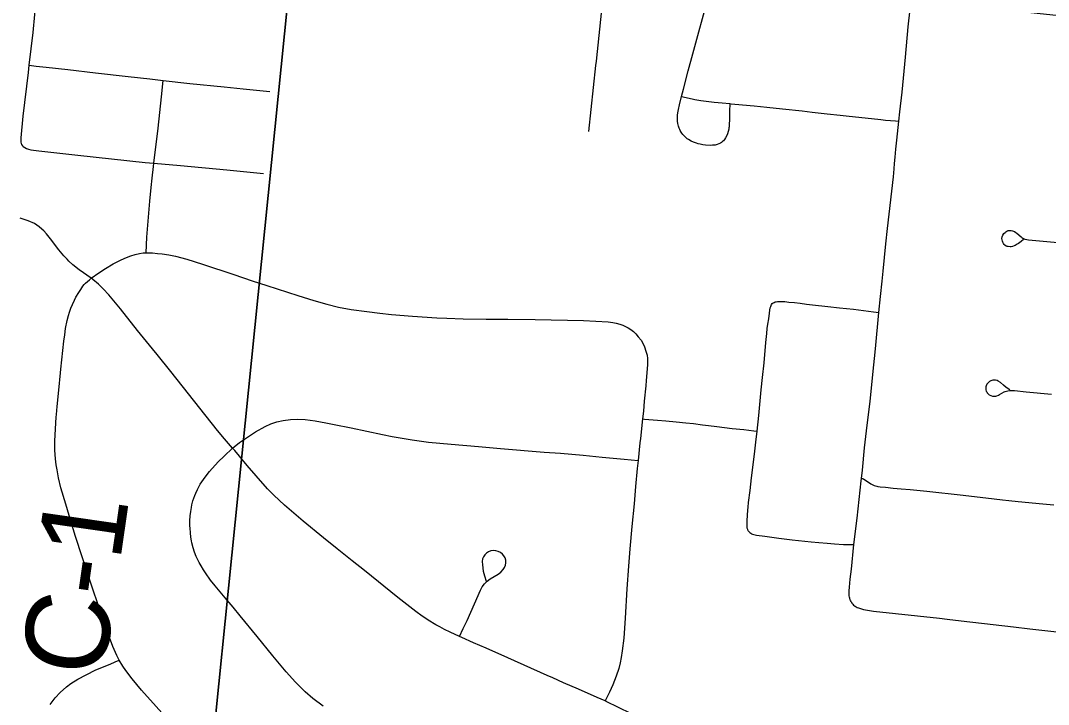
# Model space of a CAD drawing. Extents: x 0 to 34, y 0 to 22.
# Drawn here: x 24.732 to 25.43, y 15.225 to 15.69 of the extents above; entities that cross this region are included whole.
import ezdxf

# ---------------------------------------------------------------- set-up
doc = ezdxf.new("R2010")
doc.units = 0
for name, color, linetype in [('GM_X_City_Street', 7, 'Continuous'), ('GM_X_County_Road_Text', 7, 'Continuous'), ('GM_X_Section', 7, 'Continuous'), ('GM_X_Township_Road', 7, 'Continuous')]:
    doc.layers.add(name, color=color, linetype=linetype)

msp = doc.modelspace()

# ---------------------------------------------------------------- linework, layer by layer
at = {"layer": 'GM_X_City_Street'}
for points in [[(24.73283, 15.60565), (24.73251, 15.60645), (24.7323, 15.60747), (24.73225, 15.60875), (24.73229, 15.61032), (24.73382, 15.62515), (24.73728, 15.65475), (24.73786, 15.65971), (24.74042, 15.68196), (24.74161, 15.6941), (24.74276, 15.70696), (24.74368, 15.71599), (24.74424, 15.72084), (24.74506, 15.72927), (24.74595, 15.73786), (24.74734, 15.75198), (24.74828, 15.76117), (24.74867, 15.76365), (24.74921, 15.76556), (24.74985, 15.76747), (24.75048, 15.7691), (24.75167, 15.77127), (24.75276, 15.77292), (24.75573, 15.77744)], [(25.1178, 15.61473), (25.12258, 15.65953), (25.12291, 15.66253), (25.13, 15.73019), (25.13032, 15.73328)], [(25.29572, 15.29526), (25.29537, 15.29593), (25.29511, 15.29654), (25.29483, 15.29757), (25.2947, 15.2982), (25.29453, 15.29915), (25.29443, 15.29994), (25.29439, 15.3009), (25.29444, 15.30265), (25.29463, 15.30514), (25.29506, 15.31043), (25.29598, 15.31731), (25.29773, 15.33396), (25.29985, 15.35203), (25.30269, 15.37727), (25.30285, 15.37897), (25.30341, 15.3846), (25.30494, 15.39982), (25.30663, 15.41522), (25.30863, 15.43116), (25.31052, 15.44951), (25.31243, 15.467), (25.3147, 15.49177), (25.31573, 15.50261), (25.31687, 15.51305), (25.31756, 15.51982), (25.31944, 15.53833), (25.32049, 15.54882), (25.32447, 15.58375), (25.32496, 15.58931), (25.32529, 15.59294), (25.32569, 15.59715), (25.32619, 15.6026), (25.32675, 15.60874), (25.32807, 15.62169), (25.32885, 15.62799), (25.33036, 15.64138), (25.33267, 15.66524), (25.33451, 15.68579), (25.3373, 15.71007)], [(24.73786, 15.65971), (24.74257, 15.65914), (24.74925, 15.65835), (24.76409, 15.65666), (24.78292, 15.65444), (24.80504, 15.65208), (24.81981, 15.65043), (24.82881, 15.64937), (24.84682, 15.64737), (24.87006, 15.6451), (24.88299, 15.64374), (24.90115, 15.64181)], [(24.81971, 15.56738), (24.82066, 15.57668), (24.82129, 15.58284), (24.82214, 15.59086), (24.82247, 15.59307), (24.82547, 15.61681), (24.82766, 15.63812), (24.82881, 15.64937)], [(24.73283, 15.60565), (24.73327, 15.60496), (24.7338, 15.60447), (24.7348, 15.60374), (24.73593, 15.60313), (24.73733, 15.6027), (24.73901, 15.60224), (24.74446, 15.60142), (24.77091, 15.59858), (24.81651, 15.59358), (24.82247, 15.59307), (24.84059, 15.59151), (24.87205, 15.5885), (24.89678, 15.5862)], [(25.41288, 15.54123), (25.41113, 15.53984), (25.41028, 15.5392), (25.40934, 15.53855), (25.40861, 15.53806), (25.40792, 15.53765), (25.40704, 15.5372), (25.40636, 15.53691), (25.40537, 15.53657), (25.40439, 15.53635), (25.40367, 15.53632), (25.4025, 15.53643), (25.40175, 15.53658), (25.40114, 15.53684), (25.40017, 15.53744), (25.39966, 15.53793), (25.39924, 15.53847), (25.39877, 15.53937), (25.39853, 15.54005), (25.3983, 15.54108), (25.39821, 15.54188), (25.39833, 15.54313), (25.39874, 15.54427), (25.39953, 15.5454), (25.40028, 15.54613), (25.40087, 15.54658), (25.40142, 15.5469), (25.40247, 15.5473), (25.40311, 15.54743), (25.40376, 15.54749), (25.4044, 15.54746), (25.40544, 15.54725), (25.40612, 15.547), (25.40669, 15.54671), (25.4077, 15.54607), (25.40836, 15.54555), (25.41112, 15.54306), (25.41161, 15.54266), (25.4123, 15.54218), (25.41286, 15.5419), (25.41373, 15.54154), (25.41498, 15.54121), (25.41625, 15.54104), (25.41867, 15.54083), (25.4236, 15.54037), (25.43603, 15.53932)], [(25.22653, 15.34258), (25.22592, 15.34339), (25.22556, 15.34414), (25.22531, 15.34505), (25.22521, 15.34573), (25.22513, 15.34735), (25.22515, 15.34848), (25.22523, 15.35032), (25.22569, 15.35737), (25.22586, 15.35933), (25.2262, 15.36266), (25.22715, 15.37084), (25.22818, 15.37933), (25.22925, 15.38816), (25.2304, 15.39738), (25.23113, 15.40363), (25.23195, 15.41113), (25.23307, 15.42174), (25.23475, 15.43924), (25.23561, 15.44748), (25.23666, 15.45749), (25.23787, 15.47118), (25.23847, 15.47742), (25.23883, 15.48081), (25.23926, 15.48384), (25.23986, 15.48741), (25.24034, 15.49112), (25.24068, 15.49334), (25.24094, 15.4948), (25.24118, 15.49567), (25.24141, 15.49639), (25.24172, 15.49707), (25.24225, 15.49771), (25.2428, 15.49813)], [(25.2428, 15.49813), (25.24353, 15.49852), (25.24424, 15.49881), (25.24494, 15.49899), (25.24589, 15.49913), (25.24725, 15.49923), (25.24865, 15.49921), (25.25086, 15.49904), (25.2535, 15.49877), (25.25744, 15.49842), (25.26116, 15.49796), (25.2654, 15.49739), (25.26947, 15.4969), (25.27988, 15.49567), (25.28784, 15.49489), (25.29734, 15.49389), (25.31101, 15.49222), (25.3147, 15.49177)], [(25.40357, 15.43903), (25.40114, 15.44079), (25.39921, 15.44235), (25.39717, 15.4441), (25.39559, 15.44511), (25.39491, 15.44542), (25.39372, 15.44573), (25.39263, 15.44579), (25.39193, 15.44571), (25.3907, 15.44535), (25.38968, 15.44477), (25.38872, 15.44391), (25.38801, 15.44294), (25.3875, 15.44181), (25.38734, 15.44117), (25.38722, 15.43989), (25.3873, 15.43915), (25.38757, 15.43823), (25.38784, 15.43766), (25.38818, 15.43712), (25.3886, 15.43659), (25.38956, 15.43575), (25.39053, 15.4352), (25.39174, 15.43483), (25.39293, 15.43477), (25.394, 15.43492), (25.39479, 15.43514), (25.39573, 15.43552), (25.39649, 15.43589), (25.39965, 15.43767), (25.40025, 15.43795), (25.40129, 15.43833), (25.40207, 15.43854), (25.40352, 15.43877), (25.4066, 15.43869), (25.41462, 15.43787), (25.43191, 15.4361)], [(25.19902, 15.41481), (25.20465, 15.41415), (25.21498, 15.41294), (25.22288, 15.41208), (25.22984, 15.41134), (25.23195, 15.41113)], [(25.30285, 15.37897), (25.3035, 15.37885), (25.30417, 15.37857), (25.30641, 15.37715), (25.30824, 15.37586), (25.30917, 15.37527), (25.31009, 15.37475), (25.31153, 15.3741), (25.31239, 15.37381), (25.31325, 15.37358), (25.31394, 15.37343), (25.3156, 15.37319), (25.31903, 15.3729), (25.32436, 15.3724), (25.32987, 15.3719), (25.33593, 15.3714), (25.34709, 15.37027), (25.37175, 15.36752), (25.393, 15.36502), (25.39849, 15.3644), (25.40281, 15.36389), (25.40914, 15.36324), (25.42595, 15.36165), (25.43337, 15.36097)], [(25.22653, 15.34258), (25.22697, 15.34213), (25.22763, 15.34165), (25.2282, 15.34134), (25.22891, 15.34103), (25.23065, 15.34059), (25.23147, 15.34045), (25.23714, 15.33963), (25.24679, 15.33836), (25.25584, 15.33715), (25.26858, 15.33575), (25.27392, 15.33538), (25.27944, 15.33496), (25.28448, 15.33454), (25.29067, 15.33411), (25.29773, 15.33396)], [(25.29572, 15.29526), (25.29633, 15.29424), (25.29688, 15.29353), (25.29746, 15.29293), (25.29806, 15.29243), (25.2986, 15.29209), (25.29927, 15.29169), (25.29995, 15.29135), (25.30079, 15.29098), (25.30217, 15.29052), (25.30426, 15.28996), (25.30697, 15.28949), (25.31108, 15.28884), (25.35576, 15.28406), (25.36109, 15.28335), (25.37058, 15.28222), (25.39225, 15.2797), (25.40592, 15.27821), (25.41711, 15.27681), (25.43343, 15.27483), (25.44019, 15.27401), (25.45189, 15.27261), (25.45466, 15.27239), (25.46148, 15.27213)]]:
    msp.add_lwpolyline(points, dxfattribs=at)
at = {"layer": 'GM_X_Section'}
for points in [[(24.91782, 15.74839), (24.8195, 14.77309), (23.81234, 14.84657), (23.90516, 15.85455)], [(25.9263, 15.64193), (25.94936, 15.63963), (25.86182, 14.67437), (24.8195, 14.77309), (24.91782, 15.74839)]]:
    msp.add_lwpolyline(points, close=True, dxfattribs=at)
at = {"layer": 'GM_X_Township_Road'}
for points in [[(25.19242, 15.68239), (25.19487, 15.69137), (25.1971, 15.6999), (25.19909, 15.70717), (25.20276, 15.72104), (25.20421, 15.72653)], [(25.18074, 15.63837), (25.182, 15.64338), (25.1851, 15.65593), (25.18828, 15.66744), (25.19242, 15.68239)], [(25.21351, 15.63359), (25.21339, 15.63176), (25.21331, 15.63001), (25.21323, 15.62767), (25.21325, 15.62598), (25.21318, 15.62407), (25.21315, 15.62179), (25.21309, 15.62021), (25.21299, 15.61872), (25.2129, 15.61774), (25.21282, 15.61709), (25.21268, 15.61617), (25.21236, 15.6147), (25.21185, 15.61299), (25.21138, 15.61187), (25.21052, 15.61025), (25.20979, 15.60924), (25.20909, 15.60839), (25.20852, 15.60784), (25.20783, 15.60728), (25.2071, 15.60682), (25.20606, 15.60623), (25.20492, 15.6058), (25.20345, 15.60547), (25.20176, 15.60525), (25.20015, 15.60519), (25.19704, 15.60541), (25.19505, 15.60569), (25.19331, 15.606), (25.19197, 15.60628), (25.19076, 15.60664), (25.19011, 15.60685), (25.18885, 15.60736), (25.18717, 15.60818), (25.18542, 15.6092), (25.18459, 15.60977), (25.18391, 15.61031), (25.18343, 15.61074), (25.18284, 15.61134), (25.18163, 15.6127), (25.18092, 15.61361), (25.18047, 15.61425), (25.17977, 15.61539), (25.17941, 15.61603), (25.17897, 15.61702), (25.17853, 15.61837), (25.17836, 15.61911), (25.17817, 15.62015), (25.17799, 15.6217), (25.1779, 15.62316), (25.17792, 15.62443), (25.17803, 15.62584), (25.17824, 15.62737), (25.17869, 15.62961), (25.17939, 15.63267), (25.18074, 15.63837)], [(25.18074, 15.63837), (25.18799, 15.63676), (25.18968, 15.63644), (25.19383, 15.63567), (25.19922, 15.63498), (25.20284, 15.63462), (25.20831, 15.63408), (25.21351, 15.63359)], [(25.21351, 15.63359), (25.21445, 15.6335), (25.22211, 15.63283), (25.23007, 15.63204), (25.23865, 15.63126), (25.24919, 15.63006), (25.26258, 15.62862), (25.26938, 15.62786)], [(25.26938, 15.62786), (25.27954, 15.62673), (25.28836, 15.62582), (25.29453, 15.62513), (25.3053, 15.62387), (25.31603, 15.62274), (25.31904, 15.62245), (25.32581, 15.62187), (25.32807, 15.62169)], [(24.81724, 15.53218), (24.81763, 15.54287), (24.81971, 15.56738)], [(24.77987, 15.51494), (24.77184, 15.52065), (24.76748, 15.52405), (24.76481, 15.52654), (24.76355, 15.52786), (24.76144, 15.53006), (24.75793, 15.53432), (24.75233, 15.54179), (24.74956, 15.5452), (24.74784, 15.54705), (24.74647, 15.54836), (24.7445, 15.54997), (24.74134, 15.55211), (24.7371, 15.55404), (24.7316, 15.55576)], [(24.77987, 15.51494), (24.7852, 15.51873), (24.78957, 15.52161), (24.79484, 15.52473), (24.8003, 15.52745), (24.80388, 15.52893), (24.80688, 15.5301), (24.80974, 15.53102), (24.81267, 15.53179), (24.81528, 15.5321), (24.81724, 15.53218)], [(24.81724, 15.53218), (24.82155, 15.5321), (24.82487, 15.53187), (24.8281, 15.53156), (24.83257, 15.53095), (24.83718, 15.53003), (24.84493, 15.52799), (24.85553, 15.52452), (24.87677, 15.51751), (24.88912, 15.51328), (24.89913, 15.50998), (24.92029, 15.50315), (24.93096, 15.49975), (24.93998, 15.49723), (24.94789, 15.49538), (24.95648, 15.49376), (24.96708, 15.49224)], [(24.79884, 15.25549), (24.79726, 15.25861), (24.79461, 15.26483), (24.78964, 15.27817), (24.78499, 15.2917), (24.78035, 15.30581), (24.77659, 15.31733), (24.77388, 15.32565), (24.76921, 15.33958), (24.76603, 15.34997), (24.76267, 15.36141), (24.75939, 15.37249), (24.75779, 15.37927), (24.75671, 15.3847), (24.75615, 15.38807), (24.75568, 15.39217), (24.75531, 15.39822), (24.75515, 15.40442), (24.75617, 15.42048), (24.75628, 15.42231), (24.75678, 15.42784), (24.75794, 15.43895), (24.75907, 15.45066), (24.7593, 15.45313), (24.76135, 15.47225), (24.76191, 15.47655), (24.76253, 15.48079), (24.76349, 15.48625), (24.76441, 15.48973), (24.7651, 15.49194), (24.7661, 15.49462), (24.76712, 15.49709), (24.7685, 15.50004), (24.76952, 15.50199), (24.77141, 15.50521), (24.77285, 15.5074), (24.77429, 15.50945), (24.77521, 15.51067), (24.77599, 15.51153), (24.77734, 15.51279), (24.77867, 15.51393), (24.77987, 15.51494)], [(24.87575, 15.3996), (24.87046, 15.40585), (24.86573, 15.4116), (24.83402, 15.45148), (24.8247, 15.46312), (24.82158, 15.46698), (24.81144, 15.47955), (24.79972, 15.49408), (24.79178, 15.50366), (24.78799, 15.50785), (24.78486, 15.51094), (24.78104, 15.51415), (24.77987, 15.51494)], [(24.96708, 15.49224), (24.97577, 15.49116), (24.98379, 15.49039), (24.99797, 15.48919)], [(24.99797, 15.48919), (25.01464, 15.48813), (25.02141, 15.48777), (25.03249, 15.48745), (25.04793, 15.48719), (25.06281, 15.48705), (25.08139, 15.48694), (25.11409, 15.48622), (25.13093, 15.4853), (25.13396, 15.48493), (25.13639, 15.48451), (25.13876, 15.48379), (25.14088, 15.48298), (25.14302, 15.48198), (25.14442, 15.48129), (25.14613, 15.4801), (25.1481, 15.47865), (25.14961, 15.47714), (25.15132, 15.47524), (25.15323, 15.4728), (25.15435, 15.47083), (25.15553, 15.46833), (25.15645, 15.4655), (25.15731, 15.46273), (25.15764, 15.4605), (25.15761, 15.45605), (25.15674, 15.44558), (25.15642, 15.44187), (25.1554, 15.43137), (25.15478, 15.42459), (25.15419, 15.41934)], [(24.87575, 15.3996), (24.88056, 15.40329), (24.88676, 15.40744), (24.89141, 15.41056), (24.89793, 15.41419), (24.90191, 15.41594), (24.90602, 15.41735), (24.91026, 15.41834), (24.9152, 15.41894), (24.92017, 15.41913), (24.92514, 15.4189), (24.93192, 15.41804), (24.93928, 15.41679), (24.94475, 15.41564), (24.95632, 15.41332), (24.97762, 15.40885), (24.98431, 15.40749), (24.99777, 15.40518), (25.00885, 15.40363), (25.02431, 15.40221), (25.04288, 15.40067), (25.0577, 15.3993), (25.08737, 15.39689), (25.09848, 15.396), (25.11389, 15.39463), (25.12683, 15.39341), (25.14167, 15.39199), (25.15113, 15.39109)], [(25.15419, 15.41934), (25.15281, 15.4061), (25.15245, 15.40301), (25.15113, 15.39109)], [(25.15419, 15.41934), (25.15543, 15.41924), (25.16426, 15.41855), (25.1701, 15.41801), (25.17694, 15.41739), (25.18355, 15.41678), (25.18873, 15.41619), (25.19498, 15.4154), (25.19902, 15.41481)], [(24.93736, 15.22417), (24.9304, 15.22947), (24.92521, 15.234), (24.91849, 15.24053), (24.91216, 15.24743), (24.90311, 15.25851), (24.8925, 15.27151), (24.88114, 15.28548), (24.87633, 15.29142), (24.87089, 15.29784), (24.864, 15.30589), (24.861, 15.30982), (24.85747, 15.31489), (24.85614, 15.31692), (24.85454, 15.31948), (24.85319, 15.32184), (24.85236, 15.32354), (24.85126, 15.32593), (24.85006, 15.32874), (24.84916, 15.33181), (24.8483, 15.33512), (24.84801, 15.33659), (24.84761, 15.33904), (24.84728, 15.34204), (24.847, 15.34523), (24.84693, 15.34669), (24.84691, 15.3501), (24.84712, 15.35343), (24.84748, 15.35646), (24.8479, 15.35911), (24.84832, 15.36107), (24.84899, 15.36361), (24.84956, 15.36548), (24.85024, 15.36734), (24.85094, 15.36898), (24.85213, 15.37152), (24.85398, 15.37493), (24.85616, 15.37824), (24.85726, 15.37977), (24.86023, 15.38359), (24.86609, 15.3901), (24.8701, 15.39407), (24.87575, 15.3996)], [(25.02993, 15.2716), (25.02362, 15.27448), (25.01973, 15.27634), (25.01649, 15.27804), (25.01392, 15.27952), (25.00866, 15.28264), (25.00359, 15.28605), (25.00122, 15.28784), (25.00027, 15.28856), (24.99833, 15.29005), (24.98813, 15.29811), (24.96536, 15.31641), (24.95711, 15.32301), (24.9469, 15.33113), (24.93769, 15.3385), (24.92382, 15.34995), (24.91113, 15.36088), (24.90383, 15.36755), (24.89955, 15.37198), (24.89179, 15.38081), (24.8857, 15.38783), (24.87733, 15.39784), (24.87575, 15.3996)], [(25.15113, 15.39109), (25.15053, 15.38572), (25.14948, 15.37337), (25.14843, 15.36168), (25.14698, 15.34636), (25.14563, 15.331), (25.1447, 15.3193), (25.14351, 15.30384), (25.14234, 15.284), (25.14138, 15.27039), (25.14045, 15.26179), (25.13973, 15.25728), (25.13899, 15.25362), (25.13805, 15.24974), (25.13631, 15.2445), (25.134, 15.2388), (25.13165, 15.2338), (25.1288, 15.22772)], [(25.02993, 15.2716), (25.03247, 15.27699), (25.03507, 15.28252), (25.04011, 15.29384), (25.04408, 15.303), (25.0453, 15.30525), (25.04683, 15.30736), (25.04869, 15.30921), (25.05083, 15.3107), (25.05613, 15.31388), (25.05798, 15.31534), (25.05953, 15.31705), (25.06043, 15.31848), (25.06106, 15.32003), (25.06135, 15.32166), (25.0613, 15.32332), (25.06088, 15.3249), (25.06012, 15.32634), (25.05903, 15.32757), (25.05768, 15.32855), (25.05615, 15.3293), (25.05452, 15.32979), (25.05288, 15.32993), (25.05125, 15.3297), (25.04969, 15.32913), (25.04826, 15.32824), (25.04705, 15.32711), (25.04615, 15.32574), (25.04558, 15.3242), (25.04534, 15.32253), (25.04545, 15.32023), (25.04607, 15.31593), (25.04686, 15.31277), (25.04799, 15.30906)], [(25.1288, 15.22772), (25.12328, 15.23018), (25.11075, 15.23565), (25.10055, 15.24013), (25.09325, 15.24336), (25.08937, 15.24509), (25.06269, 15.25715), (25.04797, 15.26358), (25.03945, 15.26731), (25.0315, 15.27089), (25.02993, 15.2716)], [(24.75198, 15.22533), (24.75551, 15.22976), (24.75894, 15.23345), (24.76314, 15.23723), (24.76615, 15.23954), (24.77091, 15.2426), (24.77639, 15.24559), (24.78315, 15.2488), (24.79288, 15.25282), (24.79625, 15.25433), (24.79884, 15.25549)], [(24.86274, 15.16657), (24.86192, 15.16812), (24.86055, 15.17075), (24.8564, 15.17923), (24.85257, 15.1864), (24.84835, 15.19336), (24.84342, 15.20057), (24.83896, 15.20659), (24.83386, 15.21291), (24.81397, 15.23513), (24.80764, 15.24276), (24.80334, 15.24839), (24.8013, 15.25136), (24.79884, 15.25549)], [(25.20246, 15.15016), (25.20167, 15.1541), (25.20088, 15.15809), (25.19997, 15.16139), (25.19896, 15.16453), (25.19781, 15.16807), (25.19537, 15.17442), (25.19311, 15.17962), (25.18996, 15.18507), (25.18643, 15.19026), (25.18217, 15.19571), (25.17738, 15.20071), (25.17406, 15.20363), (25.17052, 15.20626), (25.16625, 15.20895), (25.16186, 15.21158), (25.14631, 15.21922), (25.12953, 15.22739), (25.1288, 15.22772)]]:
    msp.add_lwpolyline(points, dxfattribs=at)

# ---------------------------------------------------------------- texts
at = {"layer": 'GM_X_County_Road_Text'}
msp.add_text('C-1', height=0.056818, rotation=81.81109, dxfattribs=at).set_placement((24.78809, 15.24267))

doc.saveas('drawing.dxf')
